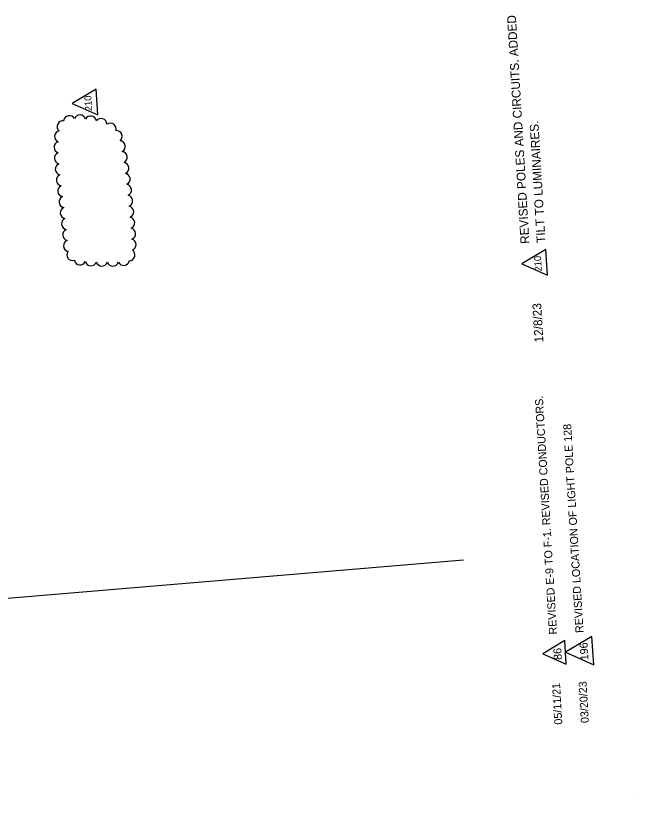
# Model space of a CAD drawing. Extents: x 928602 to 929490, y 640080 to 641338.
# Drawn here: x 929116.7 to 929489.7, y 640079.9 to 640549 of the extents above; entities that cross this region are included whole.
import ezdxf

# ---------------------------------------------------------------- set-up
doc = ezdxf.new("R2010")
doc.units = 0
for name, color, linetype in [('MatchLines_dp', 7, 'Continuous'), ('NonPlottingEle_dp', 7, 'Continuous'), ('ScratchEle_dp', 7, 'Continuous')]:
    doc.layers.add(name, color=color, linetype=linetype)

msp = doc.modelspace()

# ---------------------------------------------------------------- linework, layer by layer
at = {"layer": 'MatchLines_dp'}
msp.add_line((929489.69, 640079.89), (929489.69, 640079.89), dxfattribs=at)
at = {"layer": 'NonPlottingEle_dp'}
for points in [[(929150.55, 640496.43), (929165.9, 640489.59), (929164.98, 640505.05)], [(929419.94, 640400.33), (929435.29, 640393.49), (929434.37, 640408.95)], [(929446.06, 640167.42), (929462.95, 640159.89), (929461.94, 640176.9)], [(929432.52, 640166.61), (929446.48, 640160.39), (929445.64, 640174.45)]]:
    msp.add_lwpolyline(points, close=True, dxfattribs=at)
for centre, start, end in [((929145.07, 640482.61), 83.1793, 228.1793), ((929148.92, 640485.66), 28.5757, 173.5757), ((929155.22, 640486.14), 15.2302, 160.2302), ((929161.64, 640485.48), 8.0368, 153.0368), ((929167.89, 640483.97), 359.7129, 144.7129), ((929173.44, 640481.19), 342.1351, 127.1351), ((929143.48, 640476.64), 101.8854, 246.8854), ((929177.04, 640476.68), 310.0554, 95.0554), ((929143.18, 640470.17), 107.8578, 252.8578), ((929178.91, 640470.59), 299.0943, 84.0943), ((929143.4, 640463.63), 111.0024, 256.0024), ((929180.09, 640464.14), 296.5396, 81.5396), ((929143.91, 640457.08), 113.0093, 258.0093), ((929181.05, 640457.64), 295.2327, 80.2327), ((929144.61, 640450.54), 114.146, 259.146), ((929181.89, 640451.1), 294.403, 79.403), ((929182.64, 640444.56), 293.8162, 78.8162), ((929145.38, 640443.98), 114.2107, 259.2107), ((929146.15, 640437.43), 114.2107, 259.2107), ((929183.35, 640438), 293.384, 78.384), ((929146.92, 640430.87), 114.2107, 259.2107), ((929184, 640431.44), 292.9806, 77.9806), ((929147.69, 640424.32), 114.2107, 259.2107), ((929184.6, 640424.87), 292.413, 77.413), ((929148.37, 640417.72), 112.5418, 257.5418), ((929185.11, 640418.31), 291.5086, 76.5086), ((929185.46, 640411.75), 289.6878, 74.6878), ((929148.86, 640411.11), 110.9139, 255.9139), ((929150.8, 640405.69), 143.5021, 288.5021), ((929184.72, 640405.6), 271.491, 56.491), ((929155.3, 640403.07), 191.0416, 336.0416), ((929161.8, 640402.56), 194.9074, 339.9074), ((929168.37, 640402.35), 196.4086, 341.4086), ((929174.94, 640402.34), 198.3729, 343.3729), ((929181.41, 640402.78), 204.448, 349.448)]:
    msp.add_arc(centre, 3.46, start, end, dxfattribs=at)
at = {"layer": 'ScratchEle_dp'}
msp.add_lwpolyline([(929384.91, 640222.63), (929026.17, 640192.5), (928667.43, 640162.36)], dxfattribs=at)

# ---------------------------------------------------------------- texts
at = {"layer": 'NonPlottingEle_dp'}
for s, height, p in [('REVISED POLES AND CIRCUITS. ADDED ', 5.28, (929424.48, 640412.43)), ('210', 4.18, (929162.55, 640491.93)), ('TILT TO LUMINAIRES.', 5.28, (929434.15, 640413)), ('210', 4.18, (929431.94, 640395.84)), ('12/8/23', 5.28, (929432.86, 640353.34)), ('REVISED E-9 TO F-1. REVISED CONDUCTORS.', 4.8, (929441.03, 640178.23)), ('REVISED LOCATION OF LIGHT POLE 128', 4.8, (929456.9, 640179.17)), ('196', 4.8, (929459.85, 640162.79)), ('86', 4.8, (929443.91, 640163.02)), ('05/11/21', 4.8, (929444.25, 640124.24)), ('03/20/23', 4.8, (929460.12, 640125.19))]:
    msp.add_text(s, height=height, rotation=93.4131, dxfattribs=at).set_placement(p)

doc.saveas('drawing.dxf')
